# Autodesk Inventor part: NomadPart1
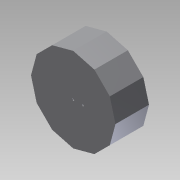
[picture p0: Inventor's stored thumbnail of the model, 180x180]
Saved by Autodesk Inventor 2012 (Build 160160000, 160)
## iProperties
Created: 2012-10
Part Number: NomadPart1
Material: Default
Document SubType Name: Modeling
Designer: TechShop Member
Density: 1 g/cm^3
Author: TechShop Member
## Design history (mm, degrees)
sketch "Sketch1"
  geometry: L1 (112.142, 0)-(97.118, -56.071); L2 (97.118, -56.071)-(56.071, -97.118); L3 (56.071, -97.118)-(0, -112.142); L4 (0, -112.142)-(-56.071, -97.118); L5 (-56.071, -97.118)-(-97.118, -56.071); L6 (-97.118, -56.071)-(-112.142, 0); L7 (-112.142, 0)-(-97.118, 56.071); L8 (-97.118, 56.071)-(-56.071, 97.118); L9 (-56.071, 97.118)-(0, 112.142); L10 (0, 112.142)-(56.071, 97.118); L11 (56.071, 97.118)-(97.118, 56.071); L12 (97.118, 56.071)-(112.142, 0); 2 further points
  constraints: 24 end point, 1 coincident, 25 other
  dimensions: "d0" = 224.28454 distance of L1.start L6.end
extrude "Extrusion1" new body sketch "Sketch1" distance "d1" = 88.9; taper "d2" = 0 deg
sketch "Sketch2"
  geometry: 2 further points
  constraints: 1 coincident
hole "Hole1" sketch "Sketch2" at (0, 0) diameter "d3" = 5.207; stored, may be unused: countersink angle "d7" = 82 deg, drill point angle "d9" = 118 deg; dims "d4" = 19.05, "d5" = 9.525, "d6" = 6.35, "d8" = 25.4
sketch "Sketch3"
  geometry: 1 further point
hole "Hole2" sketch "Sketch3" at (25.4, 0) diameter "d10" = 5.207; stored, may be unused: countersink angle "d14" = 82 deg, drill point angle "d16" = 118 deg; dims "d11" = 19.05, "d12" = 9.525, "d13" = 6.35, "d15" = 25.4
body "Solid1"
